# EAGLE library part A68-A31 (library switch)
SLIDING SWITCH Siemens, distributor Buerklin, 11G766
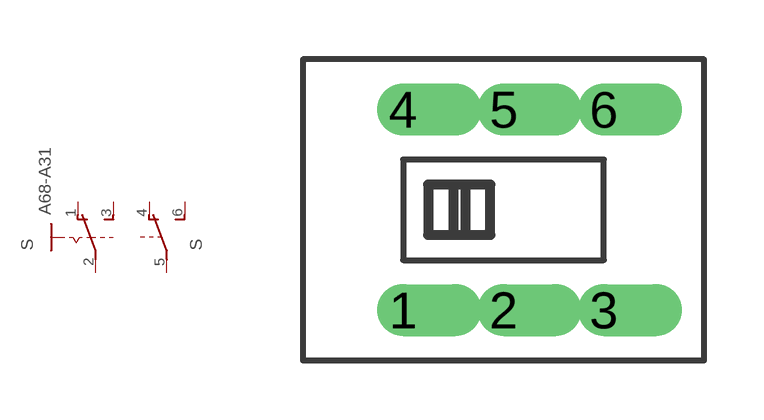
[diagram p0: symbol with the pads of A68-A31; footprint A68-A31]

Designator prefix S; gates B=U2 A=SIS-

## A68-A31  [A68-A31]
1  A:O  pas
2  A:P  pas
3  A:S  pas
4  B:O  pas
5  B:P  pas
6  B:S  pas

## Footprint A68-A31 (pad centres in mm)
SLIDING SWITCH Siemens, distributor Buerklin, 11G766
drill 0.813 offset: 1 -2.54,-2.54; 2 0,-2.54; 3 2.54,-2.54; 4 -2.54,2.54; 5 0,2.54; 6 2.54,2.54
